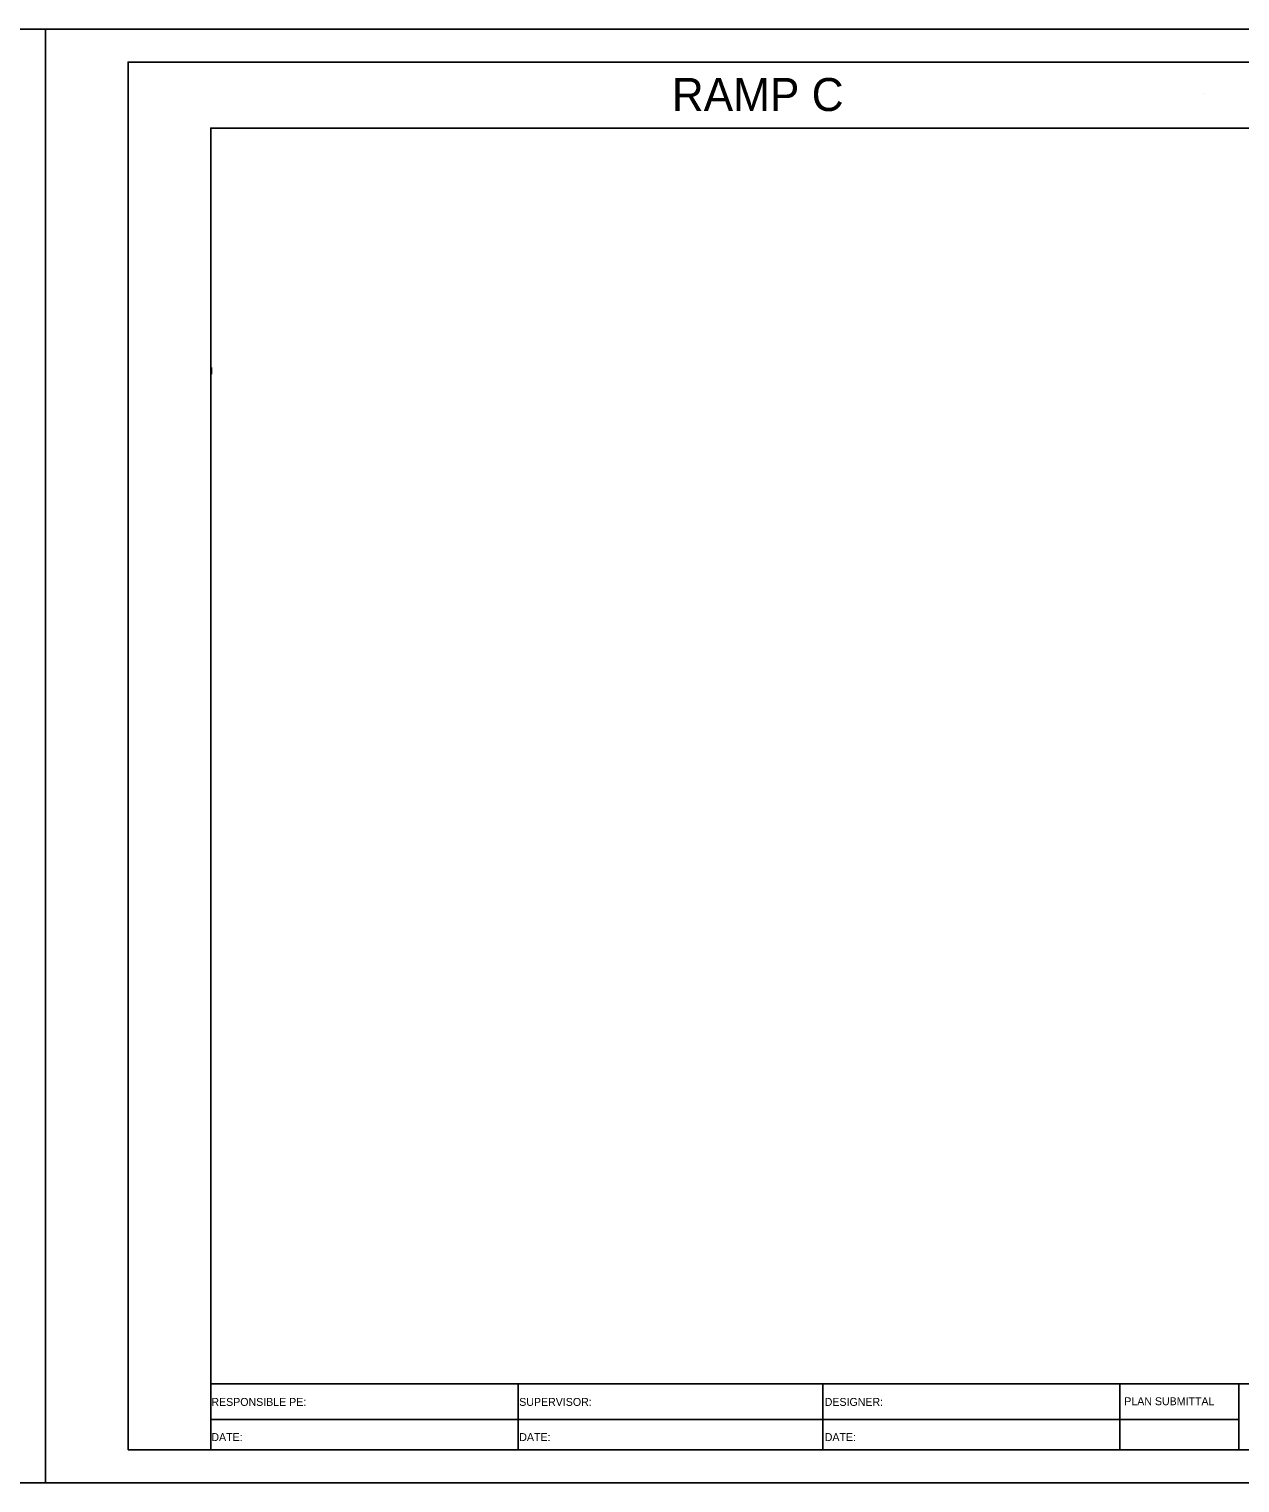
# Model space of a CAD drawing. Extents: x 1802116 to 1804496, y 250064 to 250284.
# Drawn here: x 1802453.5 to 1802636.8, y 250064.4 to 250284.4 of the extents above; entities that cross this region are included whole.
import ezdxf

# ---------------------------------------------------------------- set-up
doc = ezdxf.new("R2010")
doc.units = 0
for name, color, linetype in [('2', 7, 'Continuous'), ('ANNO-SHT', 7, 'Continuous'), ('ANNO-TXT', 7, 'Continuous'), ('AXIS', 7, 'Continuous'), ('DRAINAGE', 7, 'Continuous'), ('Level 1', 7, 'Continuous'), ('Level 62', 7, 'Continuous'), ('SHT-BDR', 7, 'Continuous'), ('SHT-BNDRY', 7, 'Continuous')]:
    doc.layers.add(name, color=color, linetype=linetype)

# ---------------------------------------------------------------- blocks, each defined once
blk = doc.blocks.new('SC47208')
at = {"layer": 'Level 1'}
blk.add_line((0, 0), (0, 0), dxfattribs=at)

msp = doc.modelspace()

# ---------------------------------------------------------------- linework, layer by layer
at = {"layer": '2'}
msp.add_lwpolyline([(1802481.12, 250233.21), (1802481.1, 250232.21)], dxfattribs=at)
msp.add_lwpolyline([(1802481.12, 250233.21), (1802481.1, 250232.21)], dxfattribs=at)
at = {"layer": 'AXIS'}
msp.add_line((1802481, 250189.42), (1802481, 250189.43), dxfattribs=at)
at = {"layer": 'Level 62'}
for points in [[(1802116, 250064.42), (1802456, 250064.42), (1802456, 250284.42), (1802116, 250284.42)], [(1802456, 250064.42), (1802796, 250064.42), (1802796, 250284.42), (1802456, 250284.42)]]:
    msp.add_lwpolyline(points, close=True, dxfattribs=at)
at = {"layer": 'SHT-BDR'}
msp.add_lwpolyline([(1802481, 250079.43), (1802781, 250079.43), (1802781, 250269.43), (1802481, 250269.43)], close=True, dxfattribs=at)
at = {"layer": 'SHT-BNDRY'}
for p, q in [((1802481, 250069.42), (1802481, 250079.43)), ((1802527.52, 250079.43), (1802527.52, 250069.42)), ((1802573.67, 250069.42), (1802573.67, 250079.43)), ((1802618.59, 250069.42), (1802618.59, 250079.43)), ((1802636.63, 250069.42), (1802636.63, 250079.43)), ((1802481, 250074.03), (1802636.63, 250074.03))]:
    msp.add_line(p, q, dxfattribs=at)
msp.add_lwpolyline([(1802468.5, 250069.42), (1802791, 250069.42), (1802791, 250279.42), (1802468.5, 250279.42)], close=True, dxfattribs=at)

# ---------------------------------------------------------------- block references
at = {"layer": 'DRAINAGE', "xscale": 0.2, "yscale": 0.20000000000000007, "rotation": -116.41666666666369}
msp.add_blockref('SC47208', (1802631.32, 250274.62), dxfattribs=at)
msp.add_blockref('SC47208', (1802631.32, 250274.62), dxfattribs=at)

# ---------------------------------------------------------------- texts
at = {"layer": 'ANNO-SHT'}
msp.add_text('                 RAMP C                 ', height=4.9995, rotation=360, dxfattribs=at).set_placement((1802519.21, 250272.02))
at = {"layer": 'ANNO-TXT'}
for s, p in [('RESPONSIBLE PE:', (1802481.1, 250076.08)), ('SUPERVISOR:', (1802527.7, 250076.08)), ('DESIGNER:', (1802573.94, 250076.08)), ('PLAN SUBMITTAL', (1802619.28, 250076.18)), ('DATE:', (1802481.1, 250070.76)), ('DATE:', (1802527.7, 250070.76)), ('DATE:', (1802573.94, 250070.76))]:
    msp.add_text(s, height=1.2, rotation=360, dxfattribs=at).set_placement(p)

doc.saveas('drawing.dxf')
